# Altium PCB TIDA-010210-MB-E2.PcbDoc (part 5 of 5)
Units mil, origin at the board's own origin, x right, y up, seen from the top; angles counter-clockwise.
Board outline 11811.02 x 8661.42 mil, 4 copper layers (Top Layer, Gnd Layer, Pwr Layer, Bottom Layer), stack 94.4 mil thick; 473 components, 257 nets, 1291 pads, 289 vias.
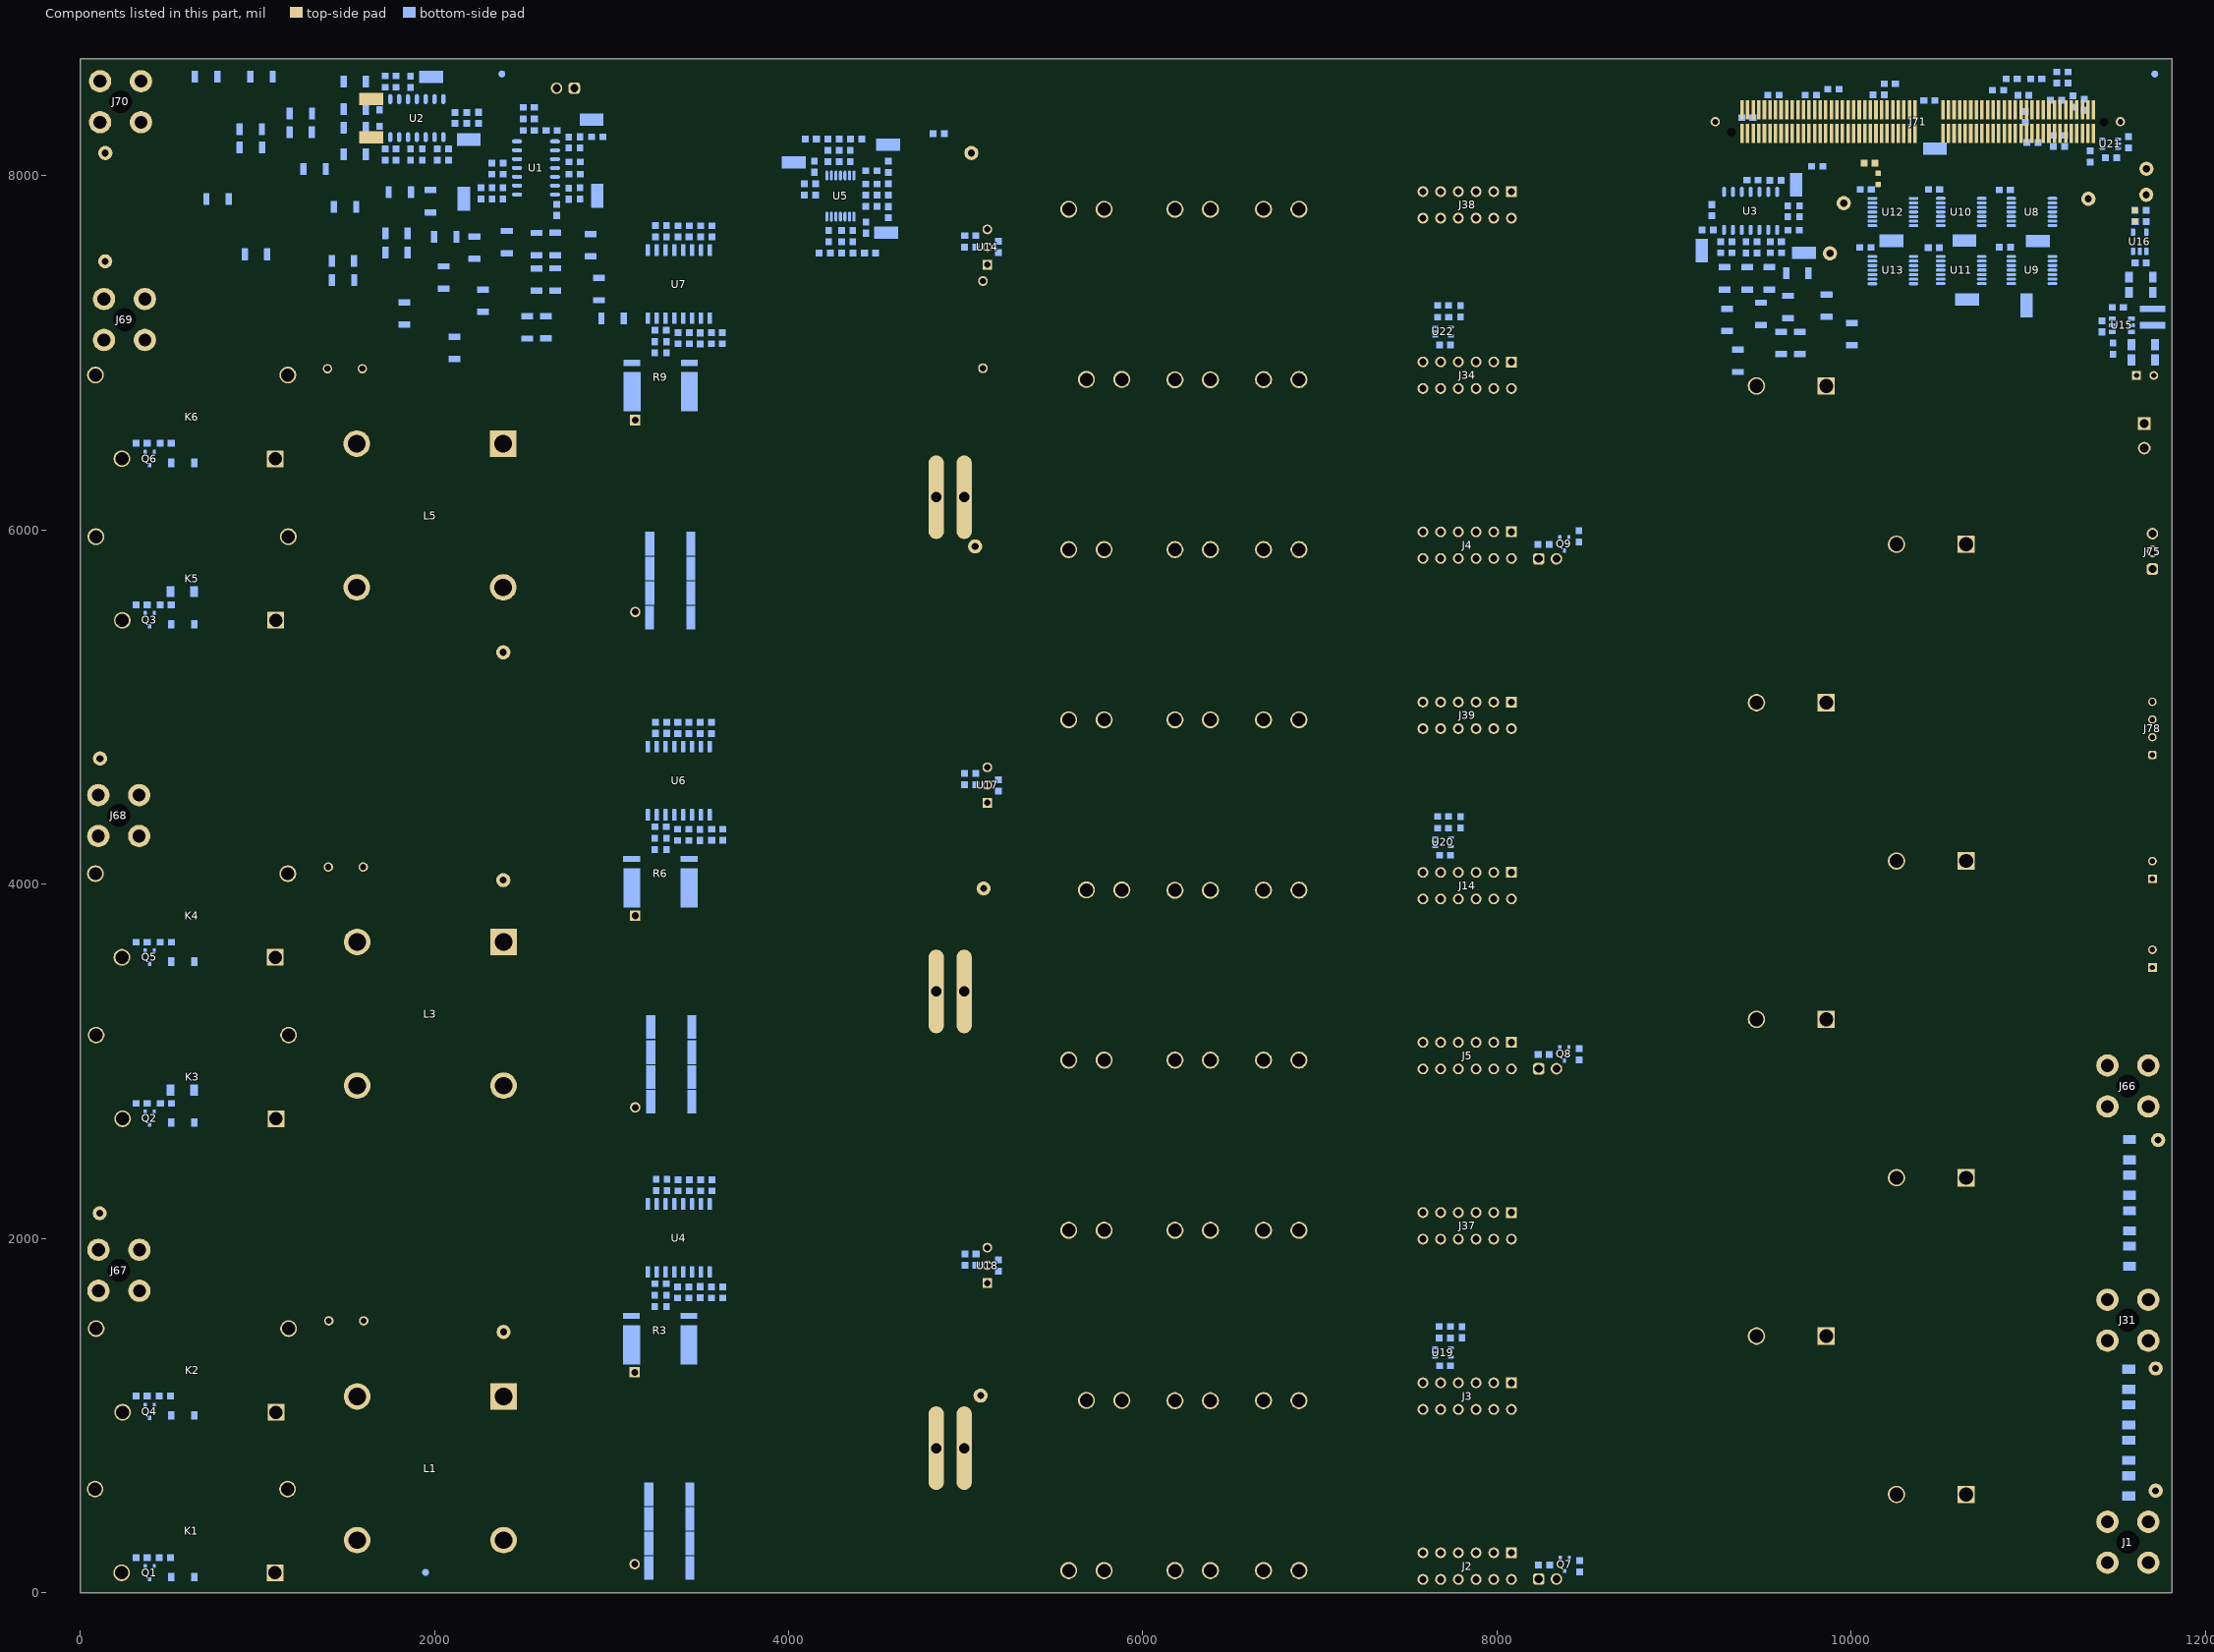
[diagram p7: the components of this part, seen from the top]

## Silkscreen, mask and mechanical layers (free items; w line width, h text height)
Top Overlay:
  circle w10: c11629.2,5774 r5.83
  circle w10: c11634,4724 r5.83
  circle w10: c5053,6152.34 r10.8
  circle w10: c5056,3424 r13.34
  circle w10: c5060,778 r11
  lines w6: 2642.84,8450.92 2649.84,8443.92 2830.16,8443.92 2840,8453.76 2840,8524.23 2840,8534.07 2830.16,8543.92 2659.68,8543.92 2642.84,8527.07 2642.84,8450.92 ; 11649.8,4679.8 11750.2,4679.8 11750.2,5080.2 11649.8,5080.2 11649.8,4679.8 ; 11650,5738.84 11657.84,5731 11742.16,5731 11747.2,5736.04 11747.2,6012.12 11730.32,6029 11659.84,6029 11650,6019.16 11650,5738.84
  lines w10: 5212.56,967.63 8165.32,967.63 ; 5212.56,967.63 5212.56,1928.26 ; 5212.56,967.63 5212.56,7 8165.32,7 8165.32,967.63 ; 5212.56,967.63 8165.32,967.63 ; 5212.56,1928.26 8165.32,1928.26 ; 5212.56,1928.26 5212.56,2888.89 ; 5212.56,1928.26 8165.32,1928.26 ; 5212.56,2888.89 8165.32,2888.89 ; 5212.56,2888.89 5212.56,3849.52 ; 5212.56,2888.89 8165.32,2888.89 ; 5212.56,3849.52 8165.32,3849.52 ; 5212.56,3849.52 5212.56,4810.15 ; 5212.56,3849.52 8165.32,3849.52 ; 5212.56,4810.15 8165.32,4810.15 ; 5212.56,4810.15 5212.56,5770.78 ; 5212.56,4810.15 8165.32,4810.15 ; 5212.56,5770.78 8165.32,5770.78 ; 5212.56,5770.78 5212.56,6731.41 ; 5212.56,5770.78 8165.32,5770.78 ; 5212.56,6731.41 8165.32,6731.41 ; 5212.56,6731.41 5212.56,7692.04 ; 5212.56,6731.41 8165.32,6731.41 ; 5212.56,7692.04 8165.32,7692.04 ; 5212.56,7692.04 8165.32,7692.04 ; 5212.56,7692.04 5212.56,8652.67 8165.32,8652.67 8165.32,7692.04 ; 8165.32,967.63 8165.32,1928.26 ; 8165.32,1928.26 8165.32,2888.89 ; 8165.32,2888.89 8165.32,3849.52 ; 8165.32,3849.52 8165.32,4810.15 ; 8165.32,4810.15 8165.32,5770.78 ; 8165.32,5770.78 8165.32,6731.41 ; 8165.32,6731.41 8165.32,7692.04 ; 8281,348 8281,2789 8951,2789 8951,348 8281,348 ; 8281,3229.78 8951,3229.78 8951,5670.78 8281,5670.78 8281,3229.78 ; 8281,6111 8281,8552 8951,8552 8951,6111 8281,6111
  text "120" at 9351,8472 h30
  text "1" at 11363,8472 h30
  text "-" at 1272,8418 h120
  text ".PRJ_Number" at 621,8407 h120
  text ".PCB_Rev" at 1309,8407 h120
  text "NEU" at 158,8195.09 h72.83
  text "119" at 9375,8117 h30
  text "2" at 11363,8117 h30
  text "TIDA-010210-GaN" at 6973,8021.04 h120
  text "GND" at 4975,8016 h72.83
  text "5V" at 11523,7987 h72.83
  text "3.3V" at 11472.5,7840 h72.83
  text "GND" at 11275.05,7758.15 h72.83
  text "DEBUG" at 9854,7733 h72.83
  text "+12V" at 9811,7447.36 h72.83
  text "PH_C" at 184,7400.84 h72.83
  text "TIDA-010210-Si-E2" at 6973,7059.41 h120
  text "For FAN Assembly" at 8912.96,6573 h120 r90
  text "TIDA-010210-GaN-E3" at 6973,6099.78 h120
  text "VSen_C" at 2291,5191 h72.83
  text "TIDA-010210-GaN-E3" at 6973,5139.15 h120
  text "PH_B" at 152,4600.2 h72.83
  text "TIDA-010210-Si-E2" at 6973,4177.52 h120
  text "VSen_B" at 2290,4139 h72.83
  text "For FAN Assembly" at 8912.96,3691.78 h120 r90
  text "TIDA-010210-GaN-E3" at 6973,3217.89 h120
  text "DC-" at 11495.39,3073.62 h72.83
  text "TIDA-010210-GaN-E3" at 6973,2257.26 h120
  text "PH_A" at 153,2033 h72.83
  text "NEU" at 11495.39,1751.12 h72.83
  text "VSen_A" at 2303,1586.07 h72.83
  text "TIDA-010210-Si-E2" at 6973,1295.63 h120
  text "For FAN Assembly" at 8912.96,810 h120 r90
  text "DC+" at 11495.39,497.62 h72.83
  text "TIDA-010210-GaN-E3" at 6973,336 h120
  text ".Layer_Name" at -89.55,-1595.49 h60
Bottom Overlay:
  circle w6: c9111,7395 r18.61
  circle w6: c9671,7633 r18.61
  lines w6: 1652,8205 1660,8205 ; 1652.98,8462.98 1662.73,8462.98 ; 2111,8138 2122,8138 ; 2289,8271 2314,8271 ; 3127,6980 3191,6980 ; 3135,1591 3199,1591 ; 3143,4175 3207,4175 ; 3363,7754 3363,7787 ; 3406,4950 3406,4971 ; 3407,2366 3407,2384 ; 3464.91,4337.2 3464.91,4344.91 3469,4349 3572,4349 3581,4358 ; 3465.96,1755 3478.96,1768 3587.41,1768 3600.41,1781 ; 3466.98,7141.2 3466.98,7145.98 3474,7153 3575,7153 3589,7167 ; 4031,7930.02 4052.76,7930.02 4047,7935.78 4047,7924.02 4052.76,7929.78 ; 4057,8148 4163,8148 ; 4118.21,7615.31 4184,7615.31 4177,7622.31 4177,7607.31 4184,7614.31 ; 4188,7599.65 4130.35,7598.93 4127.21,7595.79 4127.21,7543.79 3991.79,7543.79 3991.79,7656.21 4188,7656.21 ; 4191.9,7727.07 4400.89,7727.07 4400.89,7597.89 4391.07,7597.89 ; 4195.21,8170.89 4052.89,8170.89 4052.89,8260.11 3912.89,8260.11 3912.89,8151.89 4007.11,8151.89 4007.11,8119.89 4184,8119.89 4184,8047 4189,8042 4383,8042 4383,8170.89 4375.67,8170.89 ; 4387,8012 4395,8020 4395,8123.53 4415.47,8144 ; 4406.45,8122.17 4403,8118.72 4403,7785 4527,7785 ; 4407.49,8120.83 4606.83,8120.83 4606.83,8035.17 4775.83,8035.17 4784,8027 4784,7743 4773.74,7732.74 4592.02,7732.74 ; 4436,7632 4436,7646 ; 4603,7915 4634,7915 ; 9233.12,7656.01 9223.64,7646.53 9223.64,7527 9642,7527 9642,7618 9651,7618 ; 9354.12,7654.67 9356.11,7656.65 ; 9495.54,7656.65 9511.62,7656.65 ; 9585,7376 9610,7376 ; 9635.29,7655.33 9699,7655.33 9699,7617 ; 9739,7800 9765,7800 9760,7805 9760,7793.01 9765,7798.01 ; 2314,8271 2313,8271 2307,8265 2307,8278 2314,8271 ; 3191,6980 3184,6987 3184,6974 3190,6980 3191,6980 ; 3199,1591 3198,1591 3192,1585 3192,1598 3199,1591 ; 3207,4175 3200,4182 3200,4169 3206,4175 3207,4175 ; 3363,7787 3356,7780 3370,7780 3363,7787 ; 3406,4971 3405,4971 3399,4965 3412,4965 3406,4971 ; 3407,2384 3405,2384 3400,2379 3412,2379 3407,2384 ; 4163,8148 4161,8148 4153,8140 4153,8158 4163,8148 ; 4634,7915 4627,7908 4627,7922 4634,7915 ; 8843,7343 9135,7343 9140,7348 9140,7445 8843,7445 8843,7343
  text "A" at 9682,7623 h40
  text "A" at 9122,7385 h40
  text ".Layer_Name" at -89.55,-1595.49 h60
Top Paste:
  text ".Layer_Name" at -89.55,-1595.49 h60
Bottom Paste:
  text ".Layer_Name" at -89.55,-1595.49 h60
Top Solder:
  text ".Layer_Name" at -89.55,-1595.49 h60
  text ".Layer_Name" at -89.55,-1595.49 h60
Bottom Solder:
  text ".Layer_Name" at -89.55,-1595.49 h60
Drill Guide:
  text ".Layer_Name" at -89.55,-1595.49 h60
M1 Board Outline:
  the board outline again, w10
M2 Board Dimensions:
  rectangle: -666.55,-1012 -541.55,-887
  rectangle: -541.55,-1137 -166.55,-1012
  lines w7: -666.55,-1012 333.45,-1012 ; -541.55,-1137 -541.55,-887 ; -416.55,-1137 -416.55,-887 ; -166.55,-1137 -166.55,-887 ; 83.45,-1137 83.45,-887 ; -666.55,-1137 333.45,-1137 333.45,-887 -666.55,-887 -666.55,-1137
M3 3D STEP Top:
  text ".Layer_Name" at -89.55,-1595.49 h60
M4 3D STEP Bottom:
  text ".Layer_Name" at -89.55,-1595.49 h60
M5 Assembly Top:
  circle w10: c11702,5782 r10.05
  circle w10: c11706,4729 r10.05
  circle w10: c5121,7529 r8.25
  circle w10: c2397,6481 r20
  circle w10: c3134,6623.34 r20
  circle w10: c5033,6152.34 r20
  circle w10: c5122,4482 r9.43
  circle w10: c2401,3667 r20
  circle w10: c3138,3809.34 r20
  circle w10: c5037,3338.34 r20
  circle w10: c5121,1773 r8.59
  circle w10: c5028,776.34 r20
  circle w10: c3129,1247.34 r20
  circle w10: c2392,1105 r20
  lines w10: -958.55,-1667.17 5641.45,-1667.17 ; -958.55,-1463.83 5643.45,-1463.83 ; -958.55,-1260.5 -958.55,-1870.5 3046.45,-1870.5 5643.45,-1870.5 5643.45,-1260.5 -958.05,-1260.5 -958.05,-1870.5 617.45,-1870.5 ; 1506.45,-1870.5 1506.45,-1260.5 ; 2773.45,-1463.83 2773.45,-1260.5 ; 3613.45,-1463.83 3613.45,-1260.5 ; 4235.45,-1877 4235.45,-1674.17
  text "119" at 9340,8381 h40
  text "1" at 11362,8378 h40
  text "120" at 9335,8203 h40
  text "2" at 11361,8200 h40
  text "1" at 1091,6379 h72.83
  text "1" at 1091,5465 h72.83
  text "1" at 1094,3561 h72.83
  text "1" at 1095,2651 h72.83
  text "1" at 1094,994 h72.83
  text "1" at 1086,89 h72.83
  text "COMPONENTS MARKED 'DNP' SHOULD NOT BE POPULATED." at 486.95,-1055.5 h18
  text "ASSEMBLY VARIANT:" at 486.45,-1171 h18
  text ".VariantName" at 1522.45,-1171 h18
  text "PCB VIEWED FROM TOP SIDE" at -895.05,-1392.67 h18
  text "BOARD #:" at 1581.45,-1392.67 h18
  text ".PRJ_Number" at 2126.95,-1392.67 h18
  text "REV:" at 2971.45,-1392.67 h18
  text ".PCB_Rev" at 3262.95,-1392.67 h18
  text "SVN REV:" at 3809.45,-1392.67 h18
  text ".VersionControl_RevNumber" at 4315.45,-1392.67 h18
  text "LAYER NAME =" at -895.05,-1595.49 h18
  text "'.Layer_Name'" at -547,-1596 h18
  text "TID #:" at 1581.45,-1596 h18
  text ".TID" at 2126.95,-1596 h18
  text "PLOT NAME =" at -895.05,-1801.34 h18
  text ".plot_File_Name" at -89.55,-1801.34 h18
  text "GENERATED    :" at 1583.45,-1801.34 h18
  text ".Print_Date" at 2452.95,-1801.34 h18
  text ".Print_Time" at 3181.95,-1801.34 h18
  text "TEXAS INSTRUMENTS" at 4446.45,-1801.34 h18
M6 Assembly Bottom:
  circle w10: c11474,8206.77 r6.32
  circle w10: c11663.68,7614.91 r6.32
  circle w10: c8081.68,7026 r6.32
  circle w10: c8082.68,7991 r6.32
  circle w10: c7683.68,7094 r6.32
  circle w10: c8355.68,5932 r6.32
  circle w10: c8084.68,6064 r6.32
  circle w10: c8080.68,4142 r6.32
  circle w10: c8079.68,5101 r6.32
  circle w10: c7681.86,4210 r6.32
  circle w10: c8356.68,3052 r6.32
  circle w10: c8081.68,3181 r6.32
  circle w10: c8079.68,2220 r6.32
  circle w10: c7681.86,1331 r6.32
  circle w10: c8082,1257 r6.32
  circle w10: c8084.68,295 r6.32
  circle w10: c8360,172 r6.32
  circle w10: c3442,3992 r11.66
  circle w10: c3422,1432 r11.66
  circle w10: c369,6414 r8.06
  circle w10: c369,5501 r8.06
  circle w10: c372,3593 r8.06
  circle w10: c371.32,2687 r8.06
  circle w10: c367,1035 r8.06
  circle w10: c369,120 r8.06
  lines w10: -959.05,-1464.33 5642.95,-1464.33 ; -957.05,-1667.67 5642.95,-1667.67 ; 448.95,-1877.5 448.95,-1674.67 ; 1070.95,-1464.33 1070.95,-1261 ; 1910.95,-1464.33 1910.95,-1261 ; 3177.95,-1871 3177.95,-1261 ; 4066.95,-1871 5642.45,-1871 5642.45,-1261 -959.05,-1261 -959.05,-1871 1637.95,-1871 5642.95,-1871 5642.95,-1261
  text "COMPONENTS MARKED 'DNP' SHOULD NOT BE POPULATED." at 5435.45,-1055 h18
  text ".VariantName" at 4391.45,-1171 h18
  text "ASSEMBLY VARIANT:" at 5430.45,-1171 h18
  text ".VersionControl_RevNumber" at 368.95,-1393.17 h18
  text "SVN REV:" at 874.95,-1393.17 h18
  text ".PCB_Rev" at 1421.45,-1393.17 h18
  text "REV:" at 1712.95,-1393.17 h18
  text ".PRJ_Number" at 2557.45,-1393.17 h18
  text "BOARD #:" at 3102.95,-1393.17 h18
  text "PCB VIEWED FROM BOTTOM SIDE" at 5579.45,-1393.17 h18
  text "'.Layer_Name'" at 5263,-1569 h18
  text "LAYER NAME =" at 5589.95,-1569.49 h18
  text ".TID" at 2557.45,-1596.5 h18
  text "TID #:" at 3102.95,-1596.5 h18
  text "TEXAS INSTRUMENTS" at 237.95,-1801.84 h18
  text ".Print_Time" at 1502.45,-1801.84 h18
  text ".Print_Date" at 2231.45,-1801.84 h18
  text "GENERATED    :" at 3100.95,-1801.84 h18
  text ".plot_File_Name" at 4773.95,-1801.84 h18
  text "PLOT NAME =" at 5579.45,-1801.84 h18
M7 LPKF Text Top:
  lines w10: 9089.77,1449 9464.26,1449 ; 9089.77,3237 9464.26,3237 ; 9089.77,5025 9464.26,5025 ; 9089.77,6813 9464.26,6813 ; 9199.46,1184.2 9464.26,1449 ; 9199.46,1713.8 9464.26,1449 ; 9199.46,2972.2 9464.26,3237 ; 9199.46,3501.8 9464.26,3237 ; 9199.46,4760.2 9464.26,5025 ; 9199.46,5289.8 9464.26,5025 ; 9199.46,6548.2 9464.26,6813 ; 9464.26,1074.51 9464.26,1449 ; 9464.26,1823.49 9464.26,1449 ; 9464.26,2862.51 9464.26,3237 ; 9464.26,3611.49 9464.26,3237 ; 9464.26,4650.51 9464.26,5025 ; 9464.26,5399.49 9464.26,5025 ; 9464.26,6438.51 9464.26,6813 ; 9857.96,1074.51 9857.96,1449 ; 9857.96,1823.49 9857.96,1449 ; 9857.96,2862.51 9857.96,3237 ; 9857.96,3611.49 9857.96,3237 ; 9857.96,4650.51 9857.96,5025 ; 9857.96,5399.49 9857.96,5025 ; 9857.96,6438.51 9857.96,6813 ; 9880.32,2343 10254.81,2343 ; 9880.32,4131 10254.81,4131 ; 9880.32,5919 10254.81,5919 ; 9990.01,2078.2 10254.81,2343 ; 9990.01,2607.8 10254.81,2343 ; 9990.01,3866.2 10254.81,4131 ; 9990.01,4395.8 10254.81,4131 ; 9990.01,5654.2 10254.81,5919 ; 9990.01,6183.8 10254.81,5919 ; 10122.76,1184.2 9857.96,1449 ; 10122.76,1713.8 9857.96,1449 ; 10122.76,2972.2 9857.96,3237 ; 10122.76,3501.8 9857.96,3237 ; 10122.76,4760.2 9857.96,5025 ; 10122.76,5289.8 9857.96,5025 ; 10122.76,6548.2 9857.96,6813 ; 10163.94,6441.69 10163.94,6816.18 ; 10232.45,1449 9857.96,1449 ; 10232.45,3237 9857.96,3237 ; 10232.45,5025 9857.96,5025 ; 10232.45,6813 9857.96,6813 ; 10254.81,1968.51 10254.81,2343 ; 10254.81,2717.49 10254.81,2343 ; 10254.81,3756.51 10254.81,4131 ; 10254.81,4505.49 10254.81,4131 ; 10254.81,5544.51 10254.81,5919 ; 10254.81,6293.49 10254.81,5919 ; 10648.51,1968.51 10648.51,2343 ; 10648.51,2717.49 10648.51,2343 ; 10648.51,3756.51 10648.51,4131 ; 10648.51,4505.49 10648.51,4131 ; 10648.51,5544.51 10648.51,5919 ; 10648.51,6293.49 10648.51,5919 ; 10913.31,2078.2 10648.51,2343 ; 10913.31,2607.8 10648.51,2343 ; 10913.31,3866.2 10648.51,4131 ; 10913.31,4395.8 10648.51,4131 ; 10913.31,5654.2 10648.51,5919 ; 10913.31,6183.8 10648.51,5919 ; 11023,2343 10648.51,2343 ; 11023,4131 10648.51,4131 ; 11023,5919 10648.51,5919
M9 Title Sheet:
  drawing of 69 lines, arcs and shapes, not listed
  text "1" at 73.29,14299.5 h70
  text "2" at 2568.95,14299.5 h70
  text "3" at 5058.29,14299.5 h70
  text "4" at 7564.96,14299.5 h70
  text "5" at 16688.95,14299.5 h70
  text "6" at 19193.95,14299.5 h70
  text "A" at -1083.05,6156.5 h70
  text "A" at 20341.95,6156.5 h70
  text "B" at -1083.05,3776.5 h70
  text "B" at 20341.95,3776.5 h70
  text "C" at -1083.05,1401.5 h70
  text "C" at 20341.95,1401.5 h70
  text "PROJECT TITLE:" at 17301.95,-459.5 h45
  text ".PRJ_Title" at 17351.95,-592.83 h70
  text "DESIGNED FOR:" at 17301.95,-760.5 h45
  text ".PRJ_Customer" at 17351.95,-900.5 h70
  text "D" at -1083.05,-968.5 h70
  text "D" at 20341.95,-968.5 h70
  text "FILE NAME:" at 17301.95,-1060.5 h45
  text ".PCB_File_Name_No_Path" at 17351.95,-1180.5 h70
  text "Texas Instruments (TI) and/or its licensors do not warrant the accuracy or completeness of this specification" at 5707.45,-1342.34 h45
  text "ENGINEER:" at 17301.95,-1350.5 h45
  text "LAYOUT BY:" at 18806.95,-1350.5 h45
  text "or any information contained therein. TI and/or its licensors do not warrant that this design will meet" at 5662.46,-1455 h45
  text ".PRJ_Engineer" at 17351.95,-1505.49 h70
  text ".PCB_Layout" at 18857.45,-1505.49 h70
  text "the specifications, will be suitable for your application or fit for any particular purpose, or will operate in" at 5662.46,-1567.67 h45
  text "ALTIUM DESIGNER VERSION:" at 18806.95,-1660.5 h45
  text "an implementation. TI and/or its licensors do not warrant that the design is production worthy. You should" at 5662.46,-1680.33 h45
  text "completely validate and test your design implementation to confirm the system functionality for your application." at 5707.45,-1793 h45
  text ".print_Scale" at 17351.95,-1793.83 h70
  text ".Application_BuildNumber" at 18857.45,-1793.83 h70
  text "1" at 73.29,-2000.5 h70
  text "2" at 2568.95,-2000.5 h70
  text "3" at 5058.29,-2000.5 h70
  text "4" at 7564.96,-2000.5 h70
  text "5" at 16688.95,-2000.5 h70
  text "6" at 19193.95,-2000.5 h70
M10 Fab Notes:
  drawing of 228 lines, arcs and shapes, not listed
  text "DESIGN INFORMATION" at 18341.37,6097.03 h60
  text "(REFER ALSO ARRAY/PANEL PROFILING INFORMATION)" at 17979.81,5935.32 h60
  text "BOARD SIZE" at 17293.81,5931.03 h60
  text "300MM" at 17756.13,5803.21 h60
  text "X" at 18261.81,5803.21 h60
  text "220MM" at 18493.13,5803.21 h60
  text "Number of Layers :" at 17696.81,5606.03 h60
  text "4" at 18791.62,5596.04 h60
  text "8" at 18770.45,5469 h60
  text "MIN. TRACK WIDTH:" at 17696.81,5467.03 h60
  text "MIL" at 18947.81,5467.03 h60
  text "MIL" at 18948.45,5350 h60
  text "7.87" at 18713,5342 h60
  text "MIN. CLEARANCE:" at 17696.81,5335.03 h60
  text "12" at 18780,5222 h60
  text "MIL" at 18951.45,5216 h60
  text "MIN. VIA DRILL SIZE:" at 17696.81,5203.03 h60
  text "MINIMUM ANNULAR RING" at 17367.58,5057.04 h60
  text "EXTERNAL" at 19099.81,5057.04 h60
  text "5.90 MIL" at 18411.45,5055 h60
  text "PER" at 17567.58,4939.04 h60
  text "IPC-D-275 CLASS 2 LEVEL C" at 17787.58,4939.03 h60
  text "MIL, HOLES" at 19275.81,4826.75 h60
  text "+/-" at 18883.35,4826.04 h60
  text "+/-" at 19737.35,4826.04 h60
  text "REGISTRATION TOLERANCES:" at 17367.58,4821.03 h60
  text "METAL" at 18567.35,4821.03 h60
  text "5" at 19143.55,4821.04 h60
  text "3" at 19976.55,4821.04 h60
  text "MIL" at 20092.81,4821.03 h60
  text "MATERIAL:" at 17292.81,4611.58 h60
  text "FR-4 High Tg" at 18279.25,4471.24 h60
  text "FR-408" at 17713.81,4462.67 h60
  text "X" at 18120.35,4463.03 h60
  text "OTHER" at 19201.81,4462.67 h60
  text "OTHER" at 19433.81,4302.67 h60
  text "94.48 MIL (2.4mm) +/-10%" at 18033.91,4299.96 h60
  text "THICKNESS:" at 17367.58,4295.67 h60
  text "X" at 17905.75,4295.67 h60
  text "TOLERANCE:" at 17367.58,4137.67 h60
  text "X" at 18206.88,4137.67 h60
  text "ANSI IPC-6012 TYPE 3 CLASS 2" at 18393.82,4137.67 h60
  text "OTHER +/-" at 18393.81,3981.67 h60
  text "BOW & TWIST:" at 17367.58,3824.67 h60
  text "X" at 18206.88,3824.67 h60
  text "ANSI IPC-6012 TYPE 3 CLASS 2" at 18393.82,3824.67 h60
  text "OTHER +/-" at 18393.81,3666.17 h60
  text "COPPER THICKNESS (FINISHED):" at 17292.81,3530.67 h60
  text "X" at 19542.35,3382.03 h60
  text "1.4MIL (1oz)" at 18172.81,3377.96 h60
  text "2MIL (1.4oz)" at 18939.81,3377.96 h60
  text "2.8MIL (2oz)" at 19666.81,3377.96 h60
  text "OUTER:" at 17649.81,3373.67 h60
  text "1.4MIL (1oz)" at 18172.81,3220.96 h60
  text "2.8MIL (2oz)" at 18939.81,3220.96 h60
  text "N/A" at 19666.35,3221.32 h60
  text "X" at 18812.35,3219.03 h60
  text "INNER SIGNAL:" at 17360.73,3216.67 h60
  text "DRILLING:" at 17292.81,3077.67 h60
  text "REFERENCE:" at 17367.58,2960.67 h60
  text "X" at 18015.81,2960.67 h60
  text "AS SHOWN" at 18202.81,2960.67 h60
  text "X" at 18916.81,2960.67 h60
  text "NC_DRILL FILES" at 19053.81,2960.67 h60
  text "PTH MIN COPPER THICKNESS:" at 17367.58,2802.67 h60
  text "X" at 18717.81,2802.67 h60
  text "1MIL" at 18854.81,2802.67 h60
  text "OTHER" at 19351.81,2802.67 h60
  text "BOARD FINISH:" at 17292.81,2643.67 h60
  text "SILKSCREEN:" at 17448.03,2525.67 h60
  text "X" at 18396.81,2525.67 h60
  text "TOP" at 18522.81,2525.67 h60
  text "BOTTOM" at 19033.81,2525.67 h60
  text "X" at 18914.35,2522.03 h60
  text "SILKSCREEN COLOR:" at 17448.03,2358.67 h60
  text "X" at 18395.77,2358.67 h60
  text "WHITE" at 18522.81,2358.67 h60
  text "OTHER" at 19033.81,2358.67 h60
  text "SOLDER RESIST COLOR:" at 17448.03,2188.67 h60
  text "X" at 18015.77,2029.48 h60
  text "GREEN" at 18142.81,2029.48 h60
  text "BLUE" at 18733.81,2029.48 h60
  text "OTHER" at 19271.81,2029.48 h60
  text "IMMERSION GOLD (ENIG)" at 18353.81,1840.96 h60
  text "ENEPIG" at 19691.35,1837.67 h60
  text "SURFACE FINISH:" at 17292.81,1836.67 h60
  text "X" at 18166.86,1836.67 h60
  text "IMM. TIN/SILVER OR EQUIV" at 17622.35,1679.67 h60
  text "OTHER" at 19053.81,1679.67 h60
  text "ARRAY/PANEL:" at 17292.81,1500.67 h60
  text "CUT AND TRIM PER MECH LAYER 1" at 18353.81,1496.39 h60
  text "X" at 19021.35,1346.03 h60
  text "N.C. ROUTE" at 18353.81,1344.67 h60
  text "V. SCORE" at 19219.81,1344.67 h60
  text "CERTIFICATION:" at 17292.81,1207.67 h60
  text "MATERIALS AND WORKMANSHIP FOR ALL PCBS" at 18017.81,1207.67 h60
  text "TO MEET OR EXCEED THE REQUIREMENTS OF:" at 18017.81,1109.67 h60
  text "X" at 17644.31,973.17 h60
  text "ANSI IPC-A-600F CLASS ->" at 17783.31,973.17 h60
  text "X" at 19422.37,973.17 h60
  text "2" at 19541.31,973.17 h60
  text "1" at 19226.31,971.67 h60
  text "3" at 19895.31,971.67 h60
  text "X" at 17646.37,813.67 h60
  text "UL 94V-0" at 17783.31,813.67 h60
  text "X" at 18458.37,813.67 h60
  text "RoHS" at 18595.31,813.67 h60
  text "OTHER" at 19239.71,813.67 h60
  text "PER ORDER" at 19636.77,813.67 h60
  text "VIA TENTING:" at 18510.35,680.03 h60
  text "X" at 19280.79,680 h60
  text "ADDITIONAL REQUIREMENTS:" at 17292.81,672.67 h60
  text "YES" at 19060.02,670.95 h60
  text "NO" at 19424.82,665.73 h60
  text "MICROSECTION:" at 17367.58,557.67 h60
  text "YES" at 18273.31,557.67 h60
  text "IMPEDANCE CONTROL:" at 18532.35,551.03 h60
  text "YES" at 19516.35,550.03 h60
  text "X" at 20055.45,537 h60
  text "NO" at 19891.82,532.73 h60
  text "REQUIRED" at 19134.81,401.53 h60
  text "BARE BOARD ELEC. TEST:" at 17367.58,398.67 h60
  text "NONE" at 18673.31,398.67 h60
  text "X" at 19007.81,398.67 h60
  text "PER ORDER" at 19726.81,398.67 h60
  text "MANUFACTURER'S UL:" at 17367.58,241.67 h60
  text "RAIL" at 18533.31,237.39 h60
  text "METAL" at 19025.12,237.39 h60
  text "X" at 19400.35,237.03 h60
  text "SILK" at 19536.81,237.39 h60
M11 Gerber Information:
  lines w10: -958.55,-1667.17 5641.45,-1667.17 ; -958.55,-1463.83 5643.45,-1463.83 ; -958.55,-1260.5 -958.55,-1870.5 3046.45,-1870.5 5643.45,-1870.5 5643.45,-1260.5 -958.05,-1260.5 -958.05,-1870.5 617.45,-1870.5 ; 1506.45,-1870.5 1506.45,-1260.5 ; 2773.45,-1463.83 2773.45,-1260.5 ; 3613.45,-1463.83 3613.45,-1260.5 ; 4235.45,-1877 4235.45,-1674.17
  text "ALL ARTWORK VIEWED FROM TOP SIDE" at -895.05,-1392.67 h60
  text "BOARD #:" at 1581.45,-1392.67 h60
  text ".PRJ_Number" at 2126.95,-1392.67 h30
  text "REV:" at 2971.45,-1392.67 h60
  text ".PCB_Rev" at 3262.95,-1392.67 h60
  text "SVN REV:" at 3809.45,-1392.67 h60
  text ".VersionControl_RevNumber" at 4315.45,-1392.67 h60
  text "TID #:" at 1581.45,-1596 h60
  text ".TID" at 2126.95,-1596 h60
  text "LAYER NAME =" at -926.05,-1597.49 h60
  text "PLOT NAME =" at -895.05,-1801.34 h60
  text ".plot_File_Name" at -89.55,-1801.34 h30
  text "GENERATED    :" at 1583.45,-1801.34 h60
  text ".Print_Date" at 2452.95,-1801.34 h60
  text ".Print_Time" at 3181.95,-1801.34 h60
  text "TEXAS INSTRUMENTS" at 4446.45,-1801.34 h60
M12 Stackup:
  drawing of 295 lines, arcs and shapes, not listed
  text "Layer" at 15601.5,7727.5 h60
  text "Name" at 16011.41,7727.5 h60
  text "Material" at 16941.16,7727.5 h60
  text "Thickness" at 17800.92,7727.5 h60
  text "Constant" at 18450.76,7727.5 h60
  text "Board Layer Stack" at 19020.62,7727.5 h60
  text "Top Overlay" at 16011.41,7607.5 h60
  text "Top Solder" at 16011.41,7487.5 h60
  text "Solder Resist" at 16941.16,7487.5 h60
  text "0.40mil" at 17800.92,7487.5 h60
  text "3.5" at 18450.76,7487.5 h60
  text "1" at 15601.5,7367.5 h60
  text "Top Layer" at 16011.41,7367.5 h60
  text "2.80mil" at 17800.92,7367.5 h60
  text "Dielectric 1" at 16011.41,7247.5 h60
  text "FR-4-High Tg" at 16941.16,7247.5 h60
  text "12.00mil" at 17800.92,7247.5 h60
  text "4.2" at 18450.76,7247.5 h60
  text "2" at 15601.5,7127.5 h60
  text "Gnd Layer" at 16011.41,7127.5 h60
  text "2.80mil" at 17800.92,7127.5 h60
  text "Dielectric2" at 16011.41,7007.5 h60
  text "FR-4-High Tg" at 16941.16,7007.5 h60
  text "59.20mil" at 17800.92,7007.5 h60
  text "4.2" at 18450.76,7007.5 h60
  text "3" at 15601.5,6887.5 h60
  text "Pwr Layer" at 16011.41,6887.5 h60
  text "2.80mil" at 17800.92,6887.5 h60
  text "Dielectric 3" at 16011.41,6767.5 h60
  text "FR-4-High Tg" at 16941.16,6767.5 h60
  text "12.00mil" at 17800.92,6767.5 h60
  text "4.2" at 18450.76,6767.5 h60
  text "4" at 15601.5,6647.5 h60
  text "Bottom Layer" at 16011.41,6647.5 h60
  text "2.80mil" at 17800.92,6647.5 h60
  text "Bottom Solder" at 16011.41,6527.5 h60
  text "Solder Resist" at 16941.16,6527.5 h60
  text "0.40mil" at 17800.92,6527.5 h60
  text "3.5" at 18450.76,6527.5 h60
  text "Bottom Overlay" at 16011.41,6407.5 h60
M13 Component Bodies Top:
  text ".Layer_Name" at -89.55,-1595.49 h60
M14 Component Bodies Bottom:
  text ".Layer_Name" at -89.55,-1595.49 h60
M15 Courtyards Top:
  text ".Layer_Name" at -89.55,-1595.49 h60
M16 Courtyards Bottom:
  text ".Layer_Name" at -89.55,-1595.49 h60
Drill Drawing:
  drawing of 182 lines, arcs and shapes, not listed
  text "Symbol" at 8168.28,13261 h72
  text "Count" at 8674.16,13261 h72
  text "Hole Size" at 9264,13261 h72
  text "Plated" at 10413.67,13261 h72
  text "Hole Length" at 10919.54,13261 h72
  text "2" at 8674.16,13111 h60
  text "33.07mil (0.840mm)" at 9264,13111 h60
  text "PTH" at 10413.67,13111 h60
  text "-" at 10919.54,13111 h60
  text "2" at 8674.16,12961 h60
  text "50.00mil (1.270mm)" at 9264,12961 h60
  text "NPTH" at 10413.67,12961 h60
  text "-" at 10919.54,12961 h60
  text "2" at 8674.16,12811 h60
  text "51.18mil (1.300mm)" at 9264,12811 h60
  text "PTH" at 10413.67,12811 h60
  text "-" at 10919.54,12811 h60
  text "C" at 8139.19,12801.01 h66.67
  text "4" at 8674.16,12661 h60
  text "31.50mil (0.800mm)" at 9264,12661 h60
  text "PTH" at 10413.67,12661 h60
  text "-" at 10919.54,12661 h60
  text "B" at 8139.19,12651.01 h66.67
  text "6" at 8674.16,12511 h60
  text "29.53mil (0.750mm)" at 9264,12511 h60
  text "PTH" at 10413.67,12511 h60
  text "-" at 10919.54,12511 h60
  text "H" at 8139.19,12501.01 h66.67
  text "6" at 8674.16,12361 h60
  text "33.47mil (0.850mm)" at 9264,12361 h60
  text "PTH" at 10413.67,12361 h60
  text "-" at 10919.54,12361 h60
  text "6" at 8674.16,12211 h60
  text "39.37mil (1.000mm)" at 9264,12211 h60
  text "PTH" at 10413.67,12211 h60
  text "-" at 10919.54,12211 h60
  text "6" at 8674.16,12061 h60
  text "59.06mil (1.500mm)" at 9264,12061 h60
  text "PTH" at 10413.67,12061 h60
  text "314.96mil (8.000mm)" at 10919.54,12061 h60
  text "7" at 8674.16,11911 h60
  text "129.92mil (3.300mm)" at 9264,11911 h60
  text "NPTH" at 10413.67,11911 h60
  text "-" at 10919.54,11911 h60
  text "11" at 8674.16,11761 h60
  text "35.43mil (0.900mm)" at 9264,11761 h60
  text "PTH" at 10413.67,11761 h60
  text "-" at 10919.54,11761 h60
  text "11" at 8674.16,11611 h60
  text "45.28mil (1.150mm)" at 9264,11611 h60
  text "PTH" at 10413.67,11611 h60
  text "-" at 10919.54,11611 h60
  text "12" at 8674.16,11461 h60
  text "98.43mil (2.500mm)" at 9264,11461 h60
  text "PTH" at 10413.67,11461 h60
  text "-" at 10919.54,11461 h60
  text "16" at 8674.16,11311 h60
  text "78.74mil (2.000mm)" at 9264,11311 h60
  text "PTH" at 10413.67,11311 h60
  text "-" at 10919.54,11311 h60
  text "18" at 8674.16,11161 h60
  text "28.00mil (0.711mm)" at 9264,11161 h60
  text "PTH" at 10413.67,11161 h60
  text "-" at 10919.54,11161 h60
  text "E" at 8139.19,11151.01 h66.67
  text "19" at 8674.16,11011 h60
  text "40.00mil (1.016mm)" at 9264,11011 h60
  text "PTH" at 10413.67,11011 h60
  text "-" at 10919.54,11011 h60
  text "A" at 8139.19,11001.01 h66.67
  text "24" at 8674.16,10861 h60
  text "74.80mil (1.900mm)" at 9264,10861 h60
  text "PTH" at 10413.67,10861 h60
  text "-" at 10919.54,10861 h60
  text "28" at 8674.16,10711 h60
  text "72.84mil (1.850mm)" at 9264,10711 h60
  text "PTH" at 10413.67,10711 h60
  text "-" at 10919.54,10711 h60
  text "54" at 8674.16,10561 h60
  text "75.00mil (1.905mm)" at 9264,10561 h60
  text "PTH" at 10413.67,10561 h60
  text "-" at 10919.54,10561 h60
  text "102" at 8674.16,10411 h60
  text "16.00mil (0.406mm)" at 9264,10411 h60
  text "PTH" at 10413.67,10411 h60
  text "-" at 10919.54,10411 h60
  text "108" at 8674.16,10261 h60
  text "40.16mil (1.020mm)" at 9264,10261 h60
  text "PTH" at 10413.67,10261 h60
  text "-" at 10919.54,10261 h60
  text "169" at 8674.16,10111 h60
  text "12.00mil (0.305mm)" at 9264,10111 h60
  text "PTH" at 10413.67,10111 h60
  text "-" at 10919.54,10111 h60
  text "D" at 8139.19,10101.01 h66.67
  text "613 Total" at 8674.16,9961 h60
  text "Slot definitions :" at 8168.28,9816.03 h60
  text "Routed Path Length" at 9200.97,9816.03 h60
  text "= Calculated from tool start centre position to tool end centre position." at 10303.64,9816.03 h60
  text "Hole Length" at 9200.97,9716.05 h60
  text "= Routed Path Length + Tool Size = Slot length as defined in the PCB layout" at 9893.77,9716.05 h60
  text "FOR 12MIL DRILL +0/-12MIL" at 8124,9536 h60
  text "FOR 16MIL DRILL +0/-16MIL" at 8123,9436 h60
  text "FOR PTH DRILL +/-3MIL" at 8122,9339 h60
  text "FOR NPTH DRILL +/-2MIL" at 8122,9246 h60
  text ".Layer_Name" at -89.55,-1595.49 h60
M17 Embedded Cavity:
  text ".Layer_Name" at -89.55,-1595.49 h60
M18 Embedded Assembly:
  text ".Layer_Name" at -89.55,-1595.49 h60
M19 Embedded Keepout:
  text ".Layer_Name" at -89.55,-1595.49 h60

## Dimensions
0,0 to 0,8661.42 on M2 Board Dimensions
0,0 to 11811.02,0 on M2 Board Dimensions
-666.55,-1137 to 333.45,-1137 on M2 Board Dimensions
